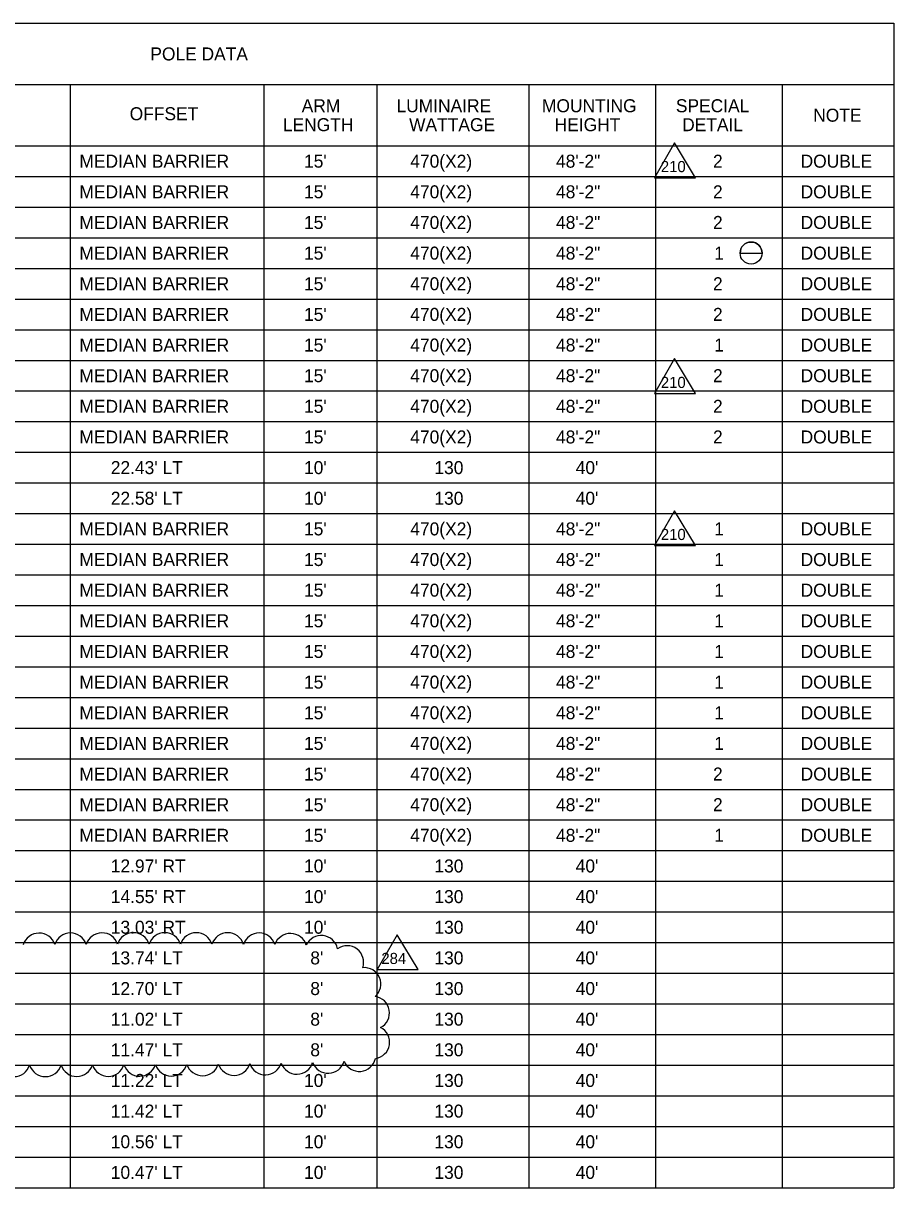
# Model space of a CAD drawing. Extents: x -816.7 to -800.7, y -2197.9 to -2187.9.
# Drawn here: x -813.23 to -808.54, y -2194.13 to -2187.86 of the extents above; entities that cross this region are included whole.
import ezdxf

# ---------------------------------------------------------------- set-up
doc = ezdxf.new("R2010")
doc.units = 0
for name, color, linetype in [('ScratchEle_dp', 7, 'Continuous'), ('SumBoxBorder_dp', 7, 'Continuous'), ('SumBoxLines_dp', 7, 'Continuous'), ('SumBoxLinesMin_dp', 7, 'Continuous'), ('TextLabel', 7, 'Continuous')]:
    doc.layers.add(name, color=color, linetype=linetype)

msp = doc.modelspace()

# ---------------------------------------------------------------- linework, layer by layer
at = {"layer": 'ScratchEle_dp'}
for points in [[(-809.7225, -2188.4998), (-809.8303, -2188.6879), (-809.6096, -2188.6879)], [(-809.7225, -2189.6621), (-809.8303, -2189.8502), (-809.6096, -2189.8502)], [(-809.7225, -2190.4807), (-809.8303, -2190.6688), (-809.6096, -2190.6688)], [(-811.215, -2192.7638), (-811.3227, -2192.9519), (-811.1021, -2192.9519)]]:
    msp.add_lwpolyline(points, close=True, dxfattribs=at)
for centre, radius, start, end in [((-813.1429, -2192.844), 0.0887, 17.81126, 162.81126), ((-812.9737, -2192.8431), 0.0887, 17.76456, 162.76456), ((-812.8044, -2192.8424), 0.0887, 17.70842, 162.70842), ((-812.6352, -2192.8419), 0.0887, 17.63916, 162.63916), ((-812.4659, -2192.8416), 0.0887, 17.55068, 162.55068), ((-812.2967, -2192.8416), 0.0887, 17.43203, 162.43203), ((-812.1275, -2192.8421), 0.0887, 17.26077, 162.26077), ((-811.9584, -2192.8432), 0.0887, 16.98047, 161.98047), ((-811.7894, -2192.8456), 0.0887, 16.37548, 161.37548), ((-811.6233, -2192.8569), 0.0887, 10.88611, 155.88611), ((-811.4843, -2192.9121), 0.0887, 340.74412, 125.74412), ((-811.3917, -2193.0297), 0.0887, 310.70221, 95.70221), ((-811.3452, -2193.185), 0.0887, 297.61139, 82.61139), ((-811.3444, -2193.3426), 0.0887, 277.92335, 62.92335), ((-811.4189, -2193.4112), 0.0888, 202.48791, 347.48791), ((-813.2782, -2193.4394), 0.0887, 197.56792, 342.56792), ((-813.1089, -2193.4391), 0.0887, 197.6205, 342.6205), ((-812.9397, -2193.4386), 0.0887, 197.68115, 342.68115), ((-812.7704, -2193.438), 0.0887, 197.75216, 342.75216), ((-812.6012, -2193.4371), 0.0887, 197.83689, 342.83689), ((-812.432, -2193.436), 0.0887, 197.94041, 342.94041), ((-812.2628, -2193.4345), 0.0887, 198.07089, 343.07089), ((-812.0936, -2193.4325), 0.0887, 198.24258, 343.24258), ((-811.9244, -2193.43), 0.0887, 198.48321, 343.48321), ((-811.7554, -2193.4265), 0.0887, 198.85675, 343.85675), ((-811.5865, -2193.4215), 0.0887, 199.56532, 344.56532)]:
    msp.add_arc(centre, radius, start, end, dxfattribs=at)
at = {"layer": 'SumBoxBorder_dp'}
for p, q in [((-815.9673, -2187.8562), (-808.5423, -2187.8562)), ((-808.5423, -2187.8562), (-808.5423, -2194.1262)), ((-808.5423, -2187.8562), (-808.5423, -2194.1262)), ((-815.9673, -2188.1862), (-808.5423, -2188.1862)), ((-815.9673, -2188.1862), (-808.5423, -2188.1862)), ((-815.9673, -2194.1262), (-808.5423, -2194.1262))]:
    msp.add_line(p, q, dxfattribs=at)
at = {"layer": 'SumBoxLines_dp'}
for p, q in [((-812.9748, -2188.1862), (-812.9748, -2194.1262)), ((-812.9748, -2188.1862), (-812.9748, -2194.1262)), ((-811.9323, -2188.1862), (-811.9323, -2194.1262)), ((-811.9323, -2188.1862), (-811.9323, -2194.1262)), ((-811.3248, -2188.1862), (-811.3248, -2194.1262)), ((-811.3248, -2188.1862), (-811.3248, -2194.1262)), ((-810.5073, -2188.1862), (-810.5073, -2194.1262)), ((-810.5073, -2188.1862), (-810.5073, -2194.1262)), ((-809.8248, -2188.1862), (-809.8248, -2194.1262)), ((-809.8248, -2188.1862), (-809.8248, -2192.3112)), ((-809.1423, -2188.1862), (-809.1423, -2194.1262)), ((-815.9673, -2188.5162), (-808.5423, -2188.5162)), ((-809.8248, -2192.4762), (-809.8248, -2194.1262))]:
    msp.add_line(p, q, dxfattribs=at)
at = {"layer": 'SumBoxLinesMin_dp'}
for p, q in [((-815.9673, -2188.5162), (-808.5423, -2188.5162)), ((-815.9673, -2188.6812), (-808.5423, -2188.6812)), ((-815.9673, -2188.6812), (-808.5423, -2188.6812)), ((-815.9673, -2188.8462), (-808.5423, -2188.8462)), ((-815.9673, -2188.8462), (-808.5423, -2188.8462)), ((-815.9673, -2189.0112), (-808.5423, -2189.0112)), ((-815.9673, -2189.0112), (-808.5423, -2189.0112)), ((-815.9673, -2189.1762), (-808.5423, -2189.1762)), ((-815.9673, -2189.1762), (-808.5423, -2189.1762)), ((-815.9673, -2189.3412), (-808.5423, -2189.3412)), ((-815.9673, -2189.3412), (-808.5423, -2189.3412)), ((-815.9673, -2189.5062), (-808.5423, -2189.5062)), ((-815.9673, -2189.5062), (-808.5423, -2189.5062)), ((-815.9673, -2189.6712), (-808.5423, -2189.6712)), ((-815.9673, -2189.6712), (-808.5423, -2189.6712)), ((-815.9673, -2189.8362), (-808.5423, -2189.8362)), ((-815.9673, -2189.8362), (-808.5423, -2189.8362)), ((-815.9673, -2190.0012), (-808.5423, -2190.0012)), ((-815.9673, -2190.0012), (-808.5423, -2190.0012)), ((-815.9673, -2190.1662), (-808.5423, -2190.1662)), ((-815.9673, -2190.1662), (-808.5423, -2190.1662)), ((-815.9673, -2190.3312), (-808.5423, -2190.3312)), ((-815.9673, -2190.3312), (-808.5423, -2190.3312)), ((-815.9673, -2190.4962), (-808.5423, -2190.4962)), ((-815.9673, -2190.4962), (-808.5423, -2190.4962)), ((-815.9673, -2190.6612), (-808.5423, -2190.6612)), ((-815.9673, -2190.6612), (-808.5423, -2190.6612)), ((-815.9673, -2190.8262), (-808.5423, -2190.8262)), ((-815.9673, -2190.8262), (-808.5423, -2190.8262)), ((-815.9673, -2190.9912), (-808.5423, -2190.9912)), ((-815.9673, -2190.9912), (-808.5423, -2190.9912)), ((-815.9673, -2191.1562), (-808.5423, -2191.1562)), ((-815.9673, -2191.1562), (-808.5423, -2191.1562)), ((-815.9673, -2191.3212), (-808.5423, -2191.3212)), ((-815.9673, -2191.3212), (-808.5423, -2191.3212)), ((-815.9673, -2191.4862), (-808.5423, -2191.4862)), ((-815.9673, -2191.4862), (-808.5423, -2191.4862)), ((-815.9673, -2191.6512), (-808.5423, -2191.6512)), ((-815.9673, -2191.6512), (-808.5423, -2191.6512)), ((-815.9673, -2191.8162), (-808.5423, -2191.8162)), ((-815.9673, -2191.8162), (-808.5423, -2191.8162)), ((-815.9673, -2191.9812), (-808.5423, -2191.9812)), ((-815.9673, -2191.9812), (-808.5423, -2191.9812)), ((-815.9673, -2192.1462), (-808.5423, -2192.1462)), ((-815.9673, -2192.1462), (-808.5423, -2192.1462)), ((-815.9673, -2192.3112), (-808.5423, -2192.3112)), ((-815.9673, -2192.3112), (-808.5423, -2192.3112)), ((-815.9673, -2192.4762), (-809.8248, -2192.4762)), ((-815.9673, -2192.4762), (-808.5423, -2192.4762)), ((-809.1423, -2192.4762), (-808.5423, -2192.4762)), ((-815.9673, -2192.6412), (-808.5423, -2192.6412)), ((-815.9673, -2192.6412), (-808.5423, -2192.6412)), ((-815.9673, -2192.8062), (-808.5423, -2192.8062)), ((-815.9673, -2192.8062), (-808.5423, -2192.8062)), ((-815.9673, -2192.9712), (-808.5423, -2192.9712)), ((-815.9673, -2192.9712), (-808.5423, -2192.9712)), ((-815.9673, -2193.1362), (-808.5423, -2193.1362)), ((-815.9673, -2193.1362), (-808.5423, -2193.1362)), ((-815.9673, -2193.3012), (-808.5423, -2193.3012)), ((-815.9673, -2193.3012), (-808.5423, -2193.3012)), ((-815.9673, -2193.4662), (-808.5423, -2193.4662)), ((-815.9673, -2193.4662), (-808.5423, -2193.4662)), ((-815.9673, -2193.6312), (-808.5423, -2193.6312)), ((-815.9673, -2193.6312), (-808.5423, -2193.6312)), ((-815.9673, -2193.7962), (-808.5423, -2193.7962)), ((-815.9673, -2193.7962), (-808.5423, -2193.7962)), ((-815.9673, -2193.9612), (-808.5423, -2193.9612)), ((-815.9673, -2193.9612), (-808.5423, -2193.9612))]:
    msp.add_line(p, q, dxfattribs=at)
at = {"layer": 'TextLabel'}
msp.add_line((-809.3691, -2189.0937), (-809.2505, -2189.0937), dxfattribs=at)
msp.add_line((-809.3691, -2189.0937), (-809.2505, -2189.0937), dxfattribs=at)
msp.add_circle((-809.3098, -2189.0937), 0.0593, dxfattribs=at)
msp.add_arc((-809.3098, -2189.0937), 0.0593, 0, 180, dxfattribs=at)

# ---------------------------------------------------------------- texts
at = {"layer": 'ScratchEle_dp'}
for s, p in [('210', (-809.7958, -2188.6578)), ('210', (-809.7958, -2189.8201)), ('210', (-809.7958, -2190.6387)), ('284', (-811.3004, -2192.9217))]:
    msp.add_text(s, height=0.05998, rotation=0, dxfattribs=at).set_placement(p)
at = {"layer": 'TextLabel'}
for s, p in [('POLE DATA', (-812.5438, -2188.0562)), ('ARM', (-811.7291, -2188.3352)), ('LUMINAIRE', (-811.2188, -2188.3352)), ('MOUNTING', (-810.4358, -2188.3352)), ('SPECIAL', (-809.715, -2188.3352)), ('OFFSET', (-812.6551, -2188.3782)), ('NOTE', (-808.9756, -2188.3862)), ('LENGTH', (-811.8305, -2188.4372)), ('WATTAGE', (-811.151, -2188.4372)), ('HEIGHT', (-810.3676, -2188.4372)), ('DETAIL', (-809.6811, -2188.4372)), ('MEDIAN BARRIER', (-812.9257, -2188.6337)), ("15'", (-811.7165, -2188.6337)), ('470(X2)', (-811.1446, -2188.6337)), ('48\'-2"', (-810.3601, -2188.6337)), ('2', (-809.515, -2188.6337)), ('DOUBLE', (-809.0434, -2188.6337)), ('MEDIAN BARRIER', (-812.9257, -2188.7987)), ("15'", (-811.7165, -2188.7987)), ('470(X2)', (-811.1446, -2188.7987)), ('48\'-2"', (-810.3601, -2188.7987)), ('2', (-809.515, -2188.7987)), ('DOUBLE', (-809.0434, -2188.7987)), ('MEDIAN BARRIER', (-812.9257, -2188.9637)), ("15'", (-811.7165, -2188.9637)), ('470(X2)', (-811.1446, -2188.9637)), ('48\'-2"', (-810.3601, -2188.9637)), ('2', (-809.515, -2188.9637)), ('DOUBLE', (-809.0434, -2188.9637)), ('MEDIAN BARRIER', (-812.9257, -2189.1287)), ("15'", (-811.7165, -2189.1287)), ('470(X2)', (-811.1446, -2189.1287)), ('48\'-2"', (-810.3601, -2189.1287)), ('1', (-809.5083, -2189.1287)), ('DOUBLE', (-809.0434, -2189.1287)), ('MEDIAN BARRIER', (-812.9257, -2189.2937)), ("15'", (-811.7165, -2189.2937)), ('470(X2)', (-811.1446, -2189.2937)), ('48\'-2"', (-810.3601, -2189.2937)), ('2', (-809.515, -2189.2937)), ('DOUBLE', (-809.0434, -2189.2937)), ('MEDIAN BARRIER', (-812.9257, -2189.4587)), ("15'", (-811.7165, -2189.4587)), ('470(X2)', (-811.1446, -2189.4587)), ('48\'-2"', (-810.3601, -2189.4587)), ('2', (-809.515, -2189.4587)), ('DOUBLE', (-809.0434, -2189.4587)), ('MEDIAN BARRIER', (-812.9257, -2189.6237)), ("15'", (-811.7165, -2189.6237)), ('470(X2)', (-811.1446, -2189.6237)), ('48\'-2"', (-810.3601, -2189.6237)), ('1', (-809.5083, -2189.6237)), ('DOUBLE', (-809.0434, -2189.6237)), ('MEDIAN BARRIER', (-812.9257, -2189.7887)), ("15'", (-811.7165, -2189.7887)), ('470(X2)', (-811.1446, -2189.7887)), ('48\'-2"', (-810.3601, -2189.7887)), ('2', (-809.515, -2189.7887)), ('DOUBLE', (-809.0434, -2189.7887)), ('MEDIAN BARRIER', (-812.9257, -2189.9537)), ("15'", (-811.7165, -2189.9537)), ('470(X2)', (-811.1446, -2189.9537)), ('48\'-2"', (-810.3601, -2189.9537)), ('2', (-809.515, -2189.9537)), ('DOUBLE', (-809.0434, -2189.9537)), ('470(X2)', (-811.1446, -2190.1187)), ('48\'-2"', (-810.3601, -2190.1187)), ('2', (-809.515, -2190.1187)), ('DOUBLE', (-809.0434, -2190.1187)), ('MEDIAN BARRIER', (-812.9257, -2190.1187)), ("15'", (-811.7165, -2190.1187)), ("22.43' LT", (-812.7567, -2190.2837)), ("10'", (-811.7165, -2190.2837)), ('130', (-811.0147, -2190.2837)), ("40'", (-810.254, -2190.2837)), ("22.58' LT", (-812.7567, -2190.4487)), ("10'", (-811.7165, -2190.4487)), ('130', (-811.0147, -2190.4487)), ("40'", (-810.254, -2190.4487)), ('MEDIAN BARRIER', (-812.9257, -2190.6137)), ("15'", (-811.7165, -2190.6137)), ('470(X2)', (-811.1446, -2190.6137)), ('48\'-2"', (-810.3601, -2190.6137)), ('1', (-809.5083, -2190.6137)), ('DOUBLE', (-809.0434, -2190.6137)), ('MEDIAN BARRIER', (-812.9257, -2190.7787)), ("15'", (-811.7165, -2190.7787)), ('470(X2)', (-811.1446, -2190.7787)), ('48\'-2"', (-810.3601, -2190.7787)), ('1', (-809.5083, -2190.7787)), ('DOUBLE', (-809.0434, -2190.7787)), ('MEDIAN BARRIER', (-812.9257, -2190.9437)), ("15'", (-811.7165, -2190.9437)), ('470(X2)', (-811.1446, -2190.9437)), ('48\'-2"', (-810.3601, -2190.9437)), ('1', (-809.5083, -2190.9437)), ('DOUBLE', (-809.0434, -2190.9437)), ('MEDIAN BARRIER', (-812.9257, -2191.1087)), ("15'", (-811.7165, -2191.1087)), ('470(X2)', (-811.1446, -2191.1087)), ('48\'-2"', (-810.3601, -2191.1087)), ('1', (-809.5083, -2191.1087)), ('DOUBLE', (-809.0434, -2191.1087)), ('MEDIAN BARRIER', (-812.9257, -2191.2737)), ("15'", (-811.7165, -2191.2737)), ('470(X2)', (-811.1446, -2191.2737)), ('48\'-2"', (-810.3601, -2191.2737)), ('1', (-809.5083, -2191.2737)), ('DOUBLE', (-809.0434, -2191.2737)), ('470(X2)', (-811.1446, -2191.4387)), ('MEDIAN BARRIER', (-812.9257, -2191.4387)), ("15'", (-811.7165, -2191.4387)), ('48\'-2"', (-810.3601, -2191.4387)), ('1', (-809.5083, -2191.4387)), ('DOUBLE', (-809.0434, -2191.4387)), ('MEDIAN BARRIER', (-812.9257, -2191.6037)), ("15'", (-811.7165, -2191.6037)), ('470(X2)', (-811.1446, -2191.6037)), ('48\'-2"', (-810.3601, -2191.6037)), ('1', (-809.5083, -2191.6037)), ('DOUBLE', (-809.0434, -2191.6037)), ('MEDIAN BARRIER', (-812.9257, -2191.7687)), ("15'", (-811.7165, -2191.7687)), ('470(X2)', (-811.1446, -2191.7687)), ('48\'-2"', (-810.3601, -2191.7687)), ('1', (-809.5083, -2191.7687)), ('DOUBLE', (-809.0434, -2191.7687)), ('MEDIAN BARRIER', (-812.9257, -2191.9337)), ("15'", (-811.7165, -2191.9337)), ('470(X2)', (-811.1446, -2191.9337)), ('48\'-2"', (-810.3601, -2191.9337)), ('2', (-809.515, -2191.9337)), ('DOUBLE', (-809.0434, -2191.9337)), ('MEDIAN BARRIER', (-812.9257, -2192.0987)), ("15'", (-811.7165, -2192.0987)), ('470(X2)', (-811.1446, -2192.0987)), ('48\'-2"', (-810.3601, -2192.0987)), ('2', (-809.515, -2192.0987)), ('DOUBLE', (-809.0434, -2192.0987)), ('MEDIAN BARRIER', (-812.9257, -2192.2637)), ("15'", (-811.7165, -2192.2637)), ('470(X2)', (-811.1446, -2192.2637)), ('48\'-2"', (-810.3601, -2192.2637)), ('1', (-809.5083, -2192.2637)), ('DOUBLE', (-809.0434, -2192.2637)), ("12.97' RT", (-812.7567, -2192.4287)), ("10'", (-811.7165, -2192.4287)), ('130', (-811.0147, -2192.4287)), ("40'", (-810.254, -2192.4287)), ("14.55' RT", (-812.7567, -2192.5937)), ("10'", (-811.7165, -2192.5937)), ('130', (-811.0147, -2192.5937)), ("40'", (-810.254, -2192.5937)), ("13.03' RT", (-812.7567, -2192.7587)), ("10'", (-811.7165, -2192.7587)), ('130', (-811.0147, -2192.7587)), ("40'", (-810.254, -2192.7587)), ("13.74' LT", (-812.7567, -2192.9237)), ("8'", (-811.6827, -2192.9237)), ('130', (-811.0147, -2192.9237)), ("40'", (-810.254, -2192.9237)), ("12.70' LT", (-812.7567, -2193.0887)), ("8'", (-811.6827, -2193.0887)), ('130', (-811.0147, -2193.0887)), ("40'", (-810.254, -2193.0887)), ("11.02' LT", (-812.7567, -2193.2537)), ("8'", (-811.6827, -2193.2537)), ('130', (-811.0147, -2193.2537)), ("40'", (-810.254, -2193.2537)), ("11.47' LT", (-812.7567, -2193.4187)), ("8'", (-811.6827, -2193.4187)), ('130', (-811.0147, -2193.4187)), ("40'", (-810.254, -2193.4187)), ("11.22' LT", (-812.7567, -2193.5837)), ("10'", (-811.7165, -2193.5837)), ('130', (-811.0147, -2193.5837)), ("40'", (-810.254, -2193.5837)), ("11.42' LT", (-812.7567, -2193.7487)), ("10'", (-811.7165, -2193.7487)), ('130', (-811.0147, -2193.7487)), ("40'", (-810.254, -2193.7487)), ("10.56' LT", (-812.7567, -2193.9137)), ("10'", (-811.7165, -2193.9137)), ('130', (-811.0147, -2193.9137)), ("40'", (-810.254, -2193.9137)), ("10.47' LT", (-812.7567, -2194.0787)), ("10'", (-811.7165, -2194.0787)), ('130', (-811.0147, -2194.0787)), ("40'", (-810.254, -2194.0787))]:
    msp.add_text(s, height=0.07, dxfattribs=at).set_placement(p)

doc.saveas('drawing.dxf')
